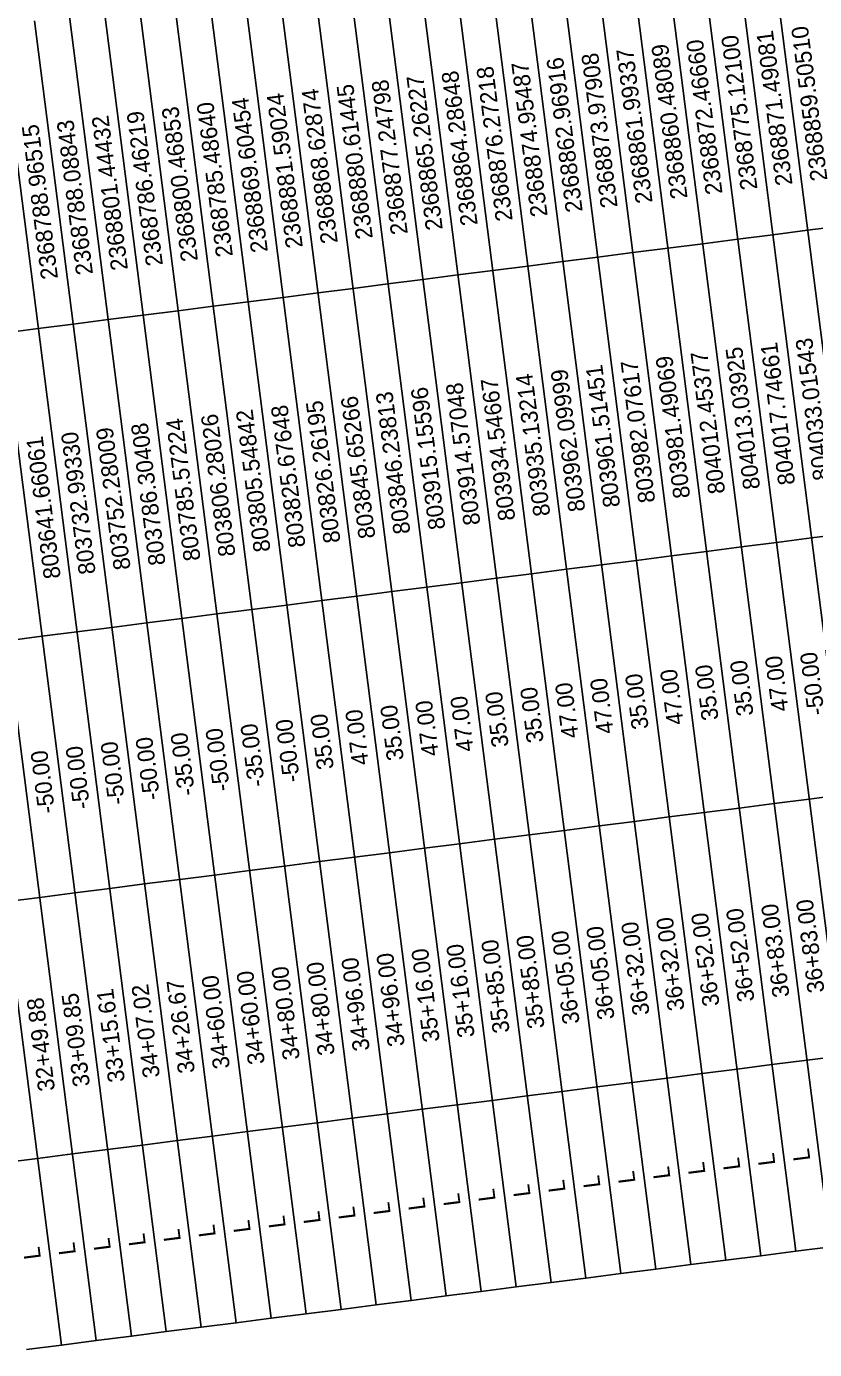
# Model space of a CAD drawing. Extents: x 2364621 to 2374814, y 792603 to 806745.
# Drawn here: x 2370303 to 2371409, y 801377 to 803235 of the extents above; entities that cross this region are included whole.
import ezdxf

# ---------------------------------------------------------------- set-up
doc = ezdxf.new("R2010")
doc.units = 0
doc.layers.add('CTL Sheet Table Cell', color=7, linetype='Continuous')
doc.layers.add('CTL Sheet Text', color=7, linetype='Continuous')

msp = doc.modelspace()

# ---------------------------------------------------------------- linework, layer by layer
at = {"layer": 'CTL Sheet Table Cell'}
for p, q in [((2371579.6, 801540.5), (2371345.4, 803374.2)), ((2371432.2, 801521.7), (2371198, 803355.4)), ((2371481.3, 801527.9), (2371247.1, 803361.7)), ((2371530.5, 801534.2), (2371296.3, 803367.9)), ((2371284.9, 801502.8), (2371050.7, 803336.6)), ((2371334, 801509.1), (2371099.8, 803342.8)), ((2371383.1, 801515.4), (2371148.9, 803349.1)), ((2371137.5, 801484), (2370903.3, 803317.8)), ((2371186.6, 801490.3), (2370952.4, 803324)), ((2371235.8, 801496.6), (2371001.5, 803330.3)), ((2370990.2, 801465.2), (2370756, 803298.9)), ((2371039.3, 801471.5), (2370805.1, 803305.2)), ((2371088.4, 801477.7), (2370854.2, 803311.5)), ((2370842.8, 801446.4), (2370608.6, 803280.1)), ((2370891.9, 801452.7), (2370657.7, 803286.4)), ((2370941, 801458.9), (2370706.8, 803292.7)), ((2370695.5, 801427.6), (2370461.3, 803261.3)), ((2370744.6, 801433.8), (2370510.4, 803267.6)), ((2370793.7, 801440.1), (2370559.5, 803273.8)), ((2370548.1, 801408.7), (2370313.9, 803242.5)), ((2370597.2, 801415), (2370363, 803248.8)), ((2370646.3, 801421.3), (2370412.1, 803255)), ((2370400.7, 801389.9), (2370166.5, 803223.7)), ((2370449.9, 801396.2), (2370215.7, 803229.9)), ((2370499, 801402.5), (2370264.8, 803236.2)), ((2370351.6, 801383.6), (2370117.4, 803217.4)), ((2371301.5, 802936), (2371350.6, 802942.3)), ((2371350.6, 802942.3), (2371399.7, 802948.5)), ((2371399.7, 802948.5), (2371448.9, 802954.8)), ((2371154.2, 802917.2), (2371203.3, 802923.4)), ((2371203.3, 802923.4), (2371252.4, 802929.7)), ((2371252.4, 802929.7), (2371301.5, 802936)), ((2371055.9, 802904.6), (2371105, 802910.9)), ((2371105, 802910.9), (2371154.2, 802917.2)), ((2370908.6, 802885.8), (2370957.7, 802892.1)), ((2370957.7, 802892.1), (2371006.8, 802898.3)), ((2371006.8, 802898.3), (2371055.9, 802904.6)), ((2370761.2, 802867), (2370810.3, 802873.2)), ((2370810.3, 802873.2), (2370859.4, 802879.5)), ((2370859.4, 802879.5), (2370908.6, 802885.8)), ((2370613.9, 802848.2), (2370663, 802854.4)), ((2370663, 802854.4), (2370712.1, 802860.7)), ((2370712.1, 802860.7), (2370761.2, 802867)), ((2370466.5, 802829.3), (2370515.6, 802835.6)), ((2370515.6, 802835.6), (2370564.7, 802841.9)), ((2370564.7, 802841.9), (2370613.9, 802848.2)), ((2370319.1, 802810.5), (2370368.3, 802816.8)), ((2370368.3, 802816.8), (2370417.4, 802823.1)), ((2370417.4, 802823.1), (2370466.5, 802829.3)), ((2370270, 802804.2), (2370319.1, 802810.5)), ((2371355.9, 802510.3), (2371405, 802516.6)), ((2371405, 802516.6), (2371454.1, 802522.8)), ((2371208.5, 802491.5), (2371257.6, 802497.7)), ((2371257.6, 802497.7), (2371306.8, 802504)), ((2371306.8, 802504), (2371355.9, 802510.3)), ((2371061.2, 802472.7), (2371110.3, 802478.9)), ((2371110.3, 802478.9), (2371159.4, 802485.2)), ((2371159.4, 802485.2), (2371208.5, 802491.5)), ((2370913.8, 802453.8), (2370962.9, 802460.1)), ((2370962.9, 802460.1), (2371012.1, 802466.4)), ((2371012.1, 802466.4), (2371061.2, 802472.7)), ((2370766.5, 802435), (2370815.6, 802441.3)), ((2370815.6, 802441.3), (2370864.7, 802447.6)), ((2370864.7, 802447.6), (2370913.8, 802453.8)), ((2370619.1, 802416.2), (2370668.2, 802422.5)), ((2370668.2, 802422.5), (2370717.3, 802428.7)), ((2370717.3, 802428.7), (2370766.5, 802435)), ((2370471.8, 802397.4), (2370520.9, 802403.6)), ((2370520.9, 802403.6), (2370570, 802409.9)), ((2370570, 802409.9), (2370619.1, 802416.2)), ((2370324.4, 802378.6), (2370373.5, 802384.8)), ((2370373.5, 802384.8), (2370422.6, 802391.1)), ((2370422.6, 802391.1), (2370471.8, 802397.4)), ((2370275.3, 802372.3), (2370324.4, 802378.6)), ((2371303.6, 802137.5), (2371352.8, 802143.8)), ((2371352.8, 802143.8), (2371401.9, 802150.1)), ((2371401.9, 802150.1), (2371451, 802156.4)), ((2371156.3, 802118.7), (2371205.4, 802125)), ((2371205.4, 802125), (2371254.5, 802131.3)), ((2371254.5, 802131.3), (2371303.6, 802137.5)), ((2371008.9, 802099.9), (2371058.1, 802106.2)), ((2371058.1, 802106.2), (2371107.2, 802112.5)), ((2371107.2, 802112.5), (2371156.3, 802118.7)), ((2370910.7, 802087.4), (2370959.8, 802093.6)), ((2370959.8, 802093.6), (2371008.9, 802099.9)), ((2370763.3, 802068.5), (2370812.5, 802074.8)), ((2370812.5, 802074.8), (2370861.6, 802081.1)), ((2370861.6, 802081.1), (2370910.7, 802087.4)), ((2370616, 802049.7), (2370665.1, 802056)), ((2370665.1, 802056), (2370714.2, 802062.3)), ((2370714.2, 802062.3), (2370763.3, 802068.5)), ((2370468.6, 802030.9), (2370517.8, 802037.2)), ((2370517.8, 802037.2), (2370566.9, 802043.4)), ((2370566.9, 802043.4), (2370616, 802049.7)), ((2370321.3, 802012.1), (2370370.4, 802018.4)), ((2370370.4, 802018.4), (2370419.5, 802024.6)), ((2370419.5, 802024.6), (2370468.6, 802030.9)), ((2370272.2, 802005.8), (2370321.3, 802012.1)), ((2371300.5, 801771.1), (2371349.6, 801777.3)), ((2371349.6, 801777.3), (2371398.8, 801783.6)), ((2371398.8, 801783.6), (2371447.9, 801789.9)), ((2371153.2, 801752.3), (2371202.3, 801758.5)), ((2371202.3, 801758.5), (2371251.4, 801764.8)), ((2371251.4, 801764.8), (2371300.5, 801771.1)), ((2371005.8, 801733.4), (2371054.9, 801739.7)), ((2371054.9, 801739.7), (2371104.1, 801746)), ((2371104.1, 801746), (2371153.2, 801752.3)), ((2370858.5, 801714.6), (2370907.6, 801720.9)), ((2370907.6, 801720.9), (2370956.7, 801727.2)), ((2370956.7, 801727.2), (2371005.8, 801733.4)), ((2370711.1, 801695.8), (2370760.2, 801702.1)), ((2370760.2, 801702.1), (2370809.4, 801708.3)), ((2370809.4, 801708.3), (2370858.5, 801714.6)), ((2370563.8, 801677), (2370612.9, 801683.3)), ((2370612.9, 801683.3), (2370662, 801689.5)), ((2370662, 801689.5), (2370711.1, 801695.8)), ((2370416.4, 801658.2), (2370465.5, 801664.4)), ((2370465.5, 801664.4), (2370514.6, 801670.7)), ((2370514.6, 801670.7), (2370563.8, 801677)), ((2370269.1, 801639.3), (2370318.2, 801645.6)), ((2370318.2, 801645.6), (2370367.3, 801651.9)), ((2370367.3, 801651.9), (2370416.4, 801658.2)), ((2371334, 801509.1), (2371383.1, 801515.4)), ((2371383.1, 801515.4), (2371432.2, 801521.7)), ((2371186.6, 801490.3), (2371235.8, 801496.6)), ((2371235.8, 801496.6), (2371284.9, 801502.8)), ((2371284.9, 801502.8), (2371334, 801509.1)), ((2371039.3, 801471.5), (2371088.4, 801477.7)), ((2371088.4, 801477.7), (2371137.5, 801484)), ((2371137.5, 801484), (2371186.6, 801490.3)), ((2370891.9, 801452.7), (2370941, 801458.9)), ((2370941, 801458.9), (2370990.2, 801465.2)), ((2370990.2, 801465.2), (2371039.3, 801471.5)), ((2370744.6, 801433.8), (2370793.7, 801440.1)), ((2370793.7, 801440.1), (2370842.8, 801446.4)), ((2370842.8, 801446.4), (2370891.9, 801452.7)), ((2370597.2, 801415), (2370646.3, 801421.3)), ((2370646.3, 801421.3), (2370695.5, 801427.6)), ((2370695.5, 801427.6), (2370744.6, 801433.8)), ((2370449.9, 801396.2), (2370499, 801402.5)), ((2370499, 801402.5), (2370548.1, 801408.7)), ((2370548.1, 801408.7), (2370597.2, 801415)), ((2370302.5, 801377.4), (2370351.6, 801383.6)), ((2370351.6, 801383.6), (2370400.7, 801389.9)), ((2370400.7, 801389.9), (2370449.9, 801396.2))]:
    msp.add_line(p, q, dxfattribs=at)

# ---------------------------------------------------------------- texts
at = {"layer": 'CTL Sheet Text'}
for s, height, p in [('2368775.12100', 23.579, (2371329.3, 803006.5)), ('2368871.49081', 23.579, (2371378.5, 803012.8)), ('2368859.50510', 23.579, (2371427.6, 803019)), ('2368860.48089', 23.579, (2371231.1, 802993.9)), ('2368872.46660', 23.579, (2371280.2, 803000.2)), ('2368862.96916', 23.579, (2371083.8, 802975.1)), ('2368873.97908', 23.579, (2371132.9, 802981.4)), ('2368861.99337', 23.579, (2371182, 802987.7)), ('2368864.28648', 23.579, (2370936.4, 802956.3)), ('2368876.27218', 23.579, (2370985.5, 802962.6)), ('2368874.95487', 23.579, (2371034.6, 802968.8)), ('2368868.62874', 23.579, (2370739.9, 802931.2)), ('2368880.61445', 23.579, (2370789.1, 802937.5)), ('2368877.24798', 23.579, (2370838.2, 802943.8)), ('2368865.26227', 23.579, (2370887.3, 802950)), ('2368785.48640', 23.579, (2370592.6, 802912.4)), ('2368869.60454', 23.579, (2370641.7, 802918.7)), ('2368881.59024', 23.579, (2370690.8, 802924.9)), ('2368801.44432', 23.579, (2370445.2, 802893.6)), ('2368786.46219', 23.579, (2370494.3, 802899.8)), ('2368800.46853', 23.579, (2370543.5, 802906.1)), ('2368788.96515', 23.579, (2370347, 802881)), ('2368788.08843', 23.579, (2370396.1, 802887.3)), ('804033.01543', 23.579, (2371431.4, 802598.7)), ('804012.45377', 23.579, (2371284, 802579.9)), ('804013.03925', 23.579, (2371333.1, 802586.1)), ('804017.74661', 23.579, (2371382.2, 802592.4)), ('803961.51451', 23.579, (2371136.6, 802561)), ('803982.07617', 23.579, (2371185.8, 802567.3)), ('803981.49069', 23.579, (2371234.9, 802573.6)), ('803934.54667', 23.579, (2370989.3, 802542.2)), ('803935.13214', 23.579, (2371038.4, 802548.5)), ('803962.09999', 23.579, (2371087.5, 802554.8)), ('803846.23813', 23.579, (2370841.9, 802523.4)), ('803915.15596', 23.579, (2370891.1, 802529.7)), ('803914.57048', 23.579, (2370940.2, 802535.9)), ('803825.67648', 23.579, (2370694.6, 802504.6)), ('803826.26195', 23.579, (2370743.7, 802510.8)), ('803845.65266', 23.579, (2370792.8, 802517.1)), ('803785.57224', 23.579, (2370547.2, 802485.8)), ('803806.28026', 23.579, (2370596.3, 802492)), ('803805.54842', 23.579, (2370645.5, 802498.3)), ('803732.99330', 23.579, (2370399.9, 802466.9)), ('803752.28009', 23.579, (2370449, 802473.2)), ('803786.30408', 23.579, (2370498.1, 802479.5)), ('803641.66061', 23.579, (2370350.8, 802460.7)), ('47.00', 23.58, (2371372.9, 802274.4)), ('-50.00', 23.58, (2371423.5, 802269.1)), ('47.00', 23.58, (2371225.6, 802255.6)), ('35.00', 23.58, (2371274.7, 802261.9)), ('35.00', 23.58, (2371323.8, 802268.1)), ('47.00', 23.58, (2371078.2, 802236.8)), ('47.00', 23.58, (2371127.3, 802243)), ('35.00', 23.58, (2371176.5, 802249.3)), ('47.00', 23.58, (2370930.9, 802217.9)), ('35.00', 23.58, (2370980, 802224.2)), ('35.00', 23.58, (2371029.1, 802230.5)), ('47.00', 23.58, (2370783.5, 802199.1)), ('35.00', 23.58, (2370832.6, 802205.4)), ('47.00', 23.58, (2370881.8, 802211.7)), ('-35.00', 23.58, (2370637.6, 802168.7)), ('-50.00', 23.58, (2370686.8, 802175)), ('35.00', 23.58, (2370734.4, 802192.9)), ('-50.00', 23.58, (2370490.3, 802149.9)), ('-35.00', 23.58, (2370539.4, 802156.2)), ('-50.00', 23.58, (2370588.5, 802162.4)), ('-50.00', 23.58, (2370342.9, 802131.1)), ('-50.00', 23.58, (2370392.1, 802137.3)), ('-50.00', 23.58, (2370441.2, 802143.6)), ('36+52.00', 23.58, (2371325.1, 801866.9)), ('36+83.00', 23.58, (2371374.3, 801873.1)), ('36+83.00', 23.58, (2371423.4, 801879.4)), ('36+32.00', 23.58, (2371177.8, 801848)), ('36+32.00', 23.58, (2371226.9, 801854.3)), ('36+52.00', 23.58, (2371276, 801860.6)), ('35+85.00', 23.58, (2371030.4, 801829.2)), ('36+05.00', 23.58, (2371079.6, 801835.5)), ('36+05.00', 23.58, (2371128.7, 801841.8)), ('35+16.00', 23.58, (2370883.1, 801810.4)), ('35+16.00', 23.58, (2370932.2, 801816.7)), ('35+85.00', 23.58, (2370981.3, 801822.9)), ('34+80.00', 23.58, (2370735.7, 801791.6)), ('34+96.00', 23.58, (2370784.8, 801797.8)), ('34+96.00', 23.58, (2370834, 801804.1)), ('34+60.00', 23.58, (2370588.4, 801772.8)), ('34+60.00', 23.58, (2370637.5, 801779)), ('34+80.00', 23.58, (2370686.6, 801785.3)), ('33+15.61', 23.58, (2370441, 801753.9)), ('34+07.02', 23.58, (2370490.1, 801760.2)), ('34+26.67', 23.58, (2370539.3, 801766.5)), ('32+49.88', 23.58, (2370342.8, 801741.4)), ('33+09.85', 23.58, (2370391.9, 801747.7)), ('L', 23.6, (2371305.4, 801630.7)), ('L', 23.6, (2371354.5, 801637)), ('L', 23.6, (2371403.6, 801643.3)), ('L', 23.6, (2371158, 801611.9)), ('L', 23.6, (2371207.1, 801618.2)), ('L', 23.6, (2371256.3, 801624.4)), ('L', 23.6, (2371010.7, 801593.1)), ('L', 23.6, (2371059.8, 801599.4)), ('L', 23.6, (2371108.9, 801605.6)), ('L', 23.6, (2370863.3, 801574.3)), ('L', 23.6, (2370912.4, 801580.5)), ('L', 23.6, (2370961.6, 801586.8)), ('L', 23.6, (2370716, 801555.4)), ('L', 23.6, (2370765.1, 801561.7)), ('L', 23.6, (2370814.2, 801568)), ('L', 23.6, (2370568.6, 801536.6)), ('L', 23.6, (2370617.7, 801542.9)), ('L', 23.6, (2370666.9, 801549.2)), ('L', 23.6, (2370421.3, 801517.8)), ('L', 23.6, (2370470.4, 801524.1)), ('L', 23.6, (2370519.5, 801530.3)), ('L', 23.6, (2370323, 801505.3)), ('L', 23.6, (2370372.1, 801511.5))]:
    msp.add_text(s, height=height, rotation=97.2784, dxfattribs=at).set_placement(p)

doc.saveas('drawing.dxf')
